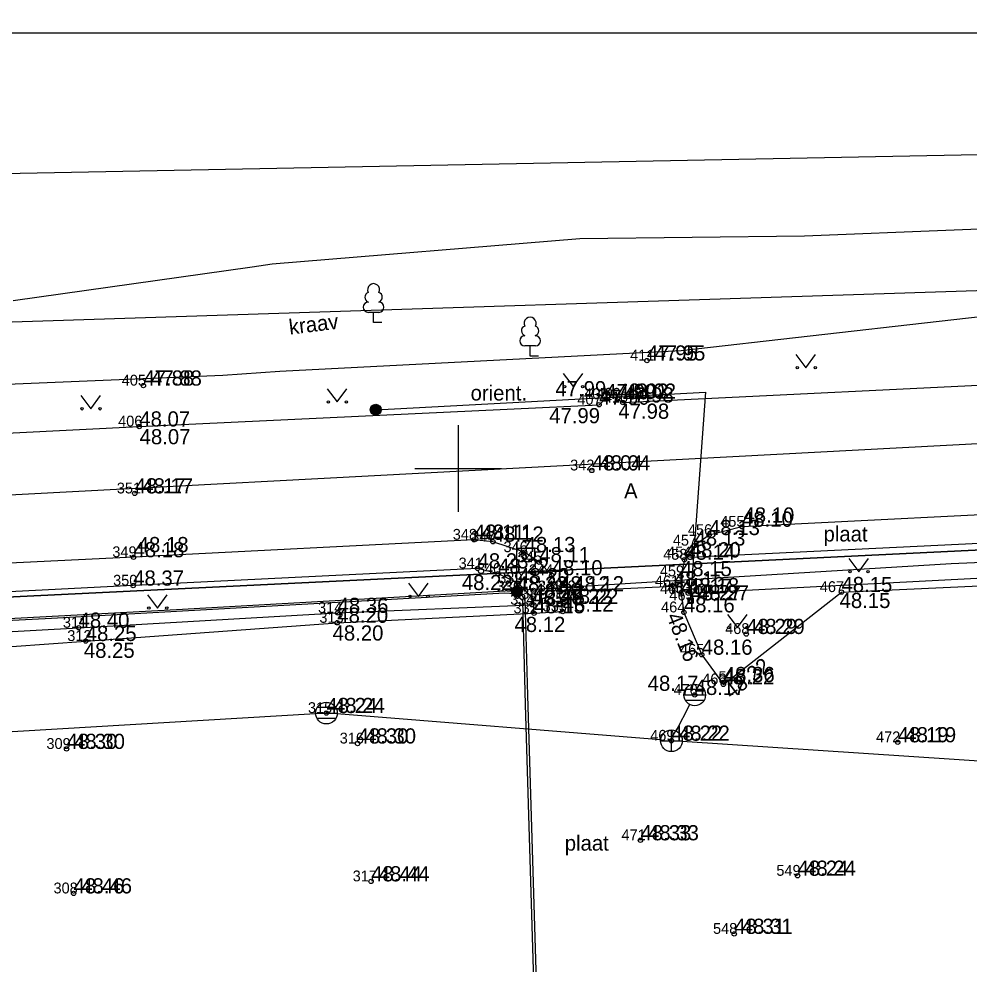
# Model space of a CAD drawing. Extents: x 640876 to 641418, y 6455595 to 6456085.
# Drawn here: x 641129.76 to 641173.59, y 6455977.11 to 6456020.73 of the extents above; entities that cross this region are included whole.
import ezdxf

# ---------------------------------------------------------------- set-up
doc = ezdxf.new("R2010")
doc.units = 0
for name, color, linetype in [('AED', 7, 'Continuous'), ('HALJASTUS', 7, 'Continuous'), ('KKAEV', 7, 'Continuous'), ('KORGUS', 7, 'Continuous'), ('MOOTKORG', 7, 'Continuous'), ('MOOTMPUNKT', 7, 'Continuous'), ('MOOTNR', 7, 'Continuous'), ('MOOTPIIR', 7, 'Continuous'), ('MPKAABEL', 7, 'Continuous'), ('PIIR', 7, 'Continuous'), ('POST', 7, 'Continuous'), ('PUU', 7, 'Continuous'), ('RAJATIS', 7, 'Continuous'), ('SKKAEV', 7, 'Continuous'), ('SKTRASS', 7, 'Continuous'), ('TEE', 7, 'Continuous'), ('VEEKOGU', 7, 'Continuous'), ('VORK', 7, 'Continuous'), ('VORMISTUS', 7, 'Continuous'), ('VTRASS', 7, 'Continuous')]:
    doc.layers.add(name, color=color, linetype=linetype)

msp = doc.modelspace()

# ---------------------------------------------------------------- linework, layer by layer
at = {"layer": 'AED'}
for p, q in [((641154.564, 6455993.886), (641154.564, 6455993.636)), ((641154.564, 6455993.886), (641154.814, 6455993.886)), ((641154.814, 6455993.886), (641154.814, 6455993.636)), ((641160.586, 6455994.045), (641160.586, 6455993.795)), ((641160.586, 6455994.045), (641160.836, 6455994.045)), ((641160.836, 6455994.045), (641160.836, 6455993.795)), ((641154.564, 6455993.636), (641154.814, 6455993.636)), ((641160.586, 6455993.795), (641160.836, 6455993.795))]:
    msp.add_line(p, q, dxfattribs=at)
for points in [[(641160.606, 6455994.253), (641178.047, 6455995.168), (641191.652, 6455995.856), (641207.752, 6455996.687), (641222.341, 6455997.449), (641221.765, 6455994.718), (641219.959, 6455985.906), (641217.708, 6455975.561), (641214.2, 6455967.017), (641207.311, 6455950.541), (641202.719, 6455939.647), (641198.916, 6455930.446)], [(641087.994, 6455978.931), (641096.846, 6455989.854), (641117.445, 6455991.822), (641132.506, 6455992.659), (641144.443, 6455993.343), (641153.401, 6455993.722)]]:
    msp.add_lwpolyline(points, dxfattribs=at)
at = {"layer": 'HALJASTUS'}
for p, q in [((641165.567, 6456005.256), (641166.03, 6456004.649)), ((641166.03, 6456004.649), (641166.476, 6456005.256)), ((641154.842, 6456004.388), (641155.305, 6456003.781)), ((641155.305, 6456003.781), (641155.751, 6456004.388)), ((641143.96, 6456003.678), (641144.423, 6456003.071)), ((641144.423, 6456003.071), (641144.869, 6456003.678)), ((641132.604, 6456003.362), (641133.067, 6456002.755)), ((641133.067, 6456002.755), (641133.513, 6456003.362)), ((641167.999, 6455995.846), (641168.463, 6455995.24)), ((641168.463, 6455995.24), (641168.908, 6455995.846)), ((641147.713, 6455994.714), (641148.177, 6455994.107)), ((641148.177, 6455994.107), (641148.622, 6455994.714)), ((641135.682, 6455994.173), (641136.145, 6455993.566)), ((641136.145, 6455993.566), (641136.591, 6455994.173)), ((641162.412, 6455993.276), (641162.875, 6455992.67)), ((641162.875, 6455992.67), (641163.321, 6455993.276))]:
    msp.add_line(p, q, dxfattribs=at)
for centre in [(641165.629, 6456004.649), (641166.458, 6456004.649), (641154.904, 6456003.781), (641155.733, 6456003.781), (641144.022, 6456003.071), (641144.851, 6456003.071), (641132.666, 6456002.755), (641133.495, 6456002.755), (641168.062, 6455995.24), (641168.89, 6455995.24), (641147.776, 6455994.107), (641148.604, 6455994.107), (641135.744, 6455993.566), (641136.573, 6455993.566), (641162.474, 6455992.67), (641163.303, 6455992.67)]:
    msp.add_circle(centre, 0.055, dxfattribs=at)
at = {"layer": 'KKAEV'}
for p, q in [((641159.828, 6455986.948), (641159.828, 6455987.948)), ((641159.328, 6455987.448), (641160.328, 6455987.448))]:
    msp.add_line(p, q, dxfattribs=at)
msp.add_circle((641159.828, 6455987.448), 0.5, dxfattribs=at)
at = {"layer": 'KORGUS'}
for centre in [(641158.702, 6456004.981), (641135.496, 6456003.825), (641156.781, 6456003.203), (641157.348, 6456003.221), (641157.594, 6456003.045), (641156.494, 6456002.943), (641135.305, 6456001.938), (641156.161, 6455999.912), (641135.093, 6455998.852), (641163.081, 6455997.316), (641150.727, 6455996.717), (641135.038, 6455995.912), (641152.702, 6455994.325), (641152.705, 6455994.33), (641167.668, 6455994.304), (641160.711, 6455993.92), (641154.689, 6455993.761), (641154.822, 6455993.407), (641160.404, 6455993.367), (641144.43, 6455992.887), (641132.837, 6455992.048), (641163.282, 6455992.37), (641162.227, 6455990.048), (641160.902, 6455989.559), (641143.927, 6455988.726), (641145.367, 6455987.321), (641159.828, 6455987.448), (641170.261, 6455987.376), (641131.95, 6455987.07), (641158.403, 6455982.857), (641165.642, 6455981.221), (641145.99, 6455980.965), (641132.276, 6455980.408), (641162.723, 6455978.543)]:
    msp.add_circle(centre, 0.1, dxfattribs=at)
at = {"layer": 'MOOTMPUNKT'}
for centre in [(641158.702, 6456004.981), (641135.496, 6456003.825), (641156.781, 6456003.203), (641157.348, 6456003.221), (641157.594, 6456003.045), (641156.494, 6456002.943), (641135.305, 6456001.938), (641156.161, 6455999.912), (641135.093, 6455998.852), (641163.081, 6455997.316), (641161.565, 6455996.932), (641150.727, 6455996.717), (641151.601, 6455996.628), (641160.895, 6455996.447), (641153.065, 6455996.145), (641135.038, 6455995.912), (641153.74, 6455995.681), (641160.425, 6455995.795), (641160.679, 6455995.901), (641150.896, 6455995.393), (641151.844, 6455995.148), (641152.772, 6455994.709), (641154.316, 6455995.079), (641160.271, 6455995.032), (641135.023, 6455994.601), (641152.702, 6455994.325), (641152.705, 6455994.33), (641154.653, 6455994.333), (641155.303, 6455994.339), (641159.942, 6455994.565), (641160.279, 6455994.218), (641160.606, 6455994.253), (641167.668, 6455994.304), (641153.465, 6455993.996), (641160.711, 6455993.92), (641144.443, 6455993.343), (641153.401, 6455993.722), (641154.689, 6455993.761), (641154.822, 6455993.407), (641160.404, 6455993.367), (641153.501, 6455993.325), (641132.506, 6455992.659), (641144.43, 6455992.887), (641132.837, 6455992.048), (641163.282, 6455992.37), (641161.226, 6455991.415), (641162.227, 6455990.048), (641162.246, 6455990.152), (641160.902, 6455989.559), (641143.927, 6455988.726), (641145.367, 6455987.321), (641159.828, 6455987.448), (641170.261, 6455987.376), (641131.95, 6455987.07), (641158.403, 6455982.857), (641165.642, 6455981.221), (641145.99, 6455980.965), (641132.276, 6455980.408), (641162.723, 6455978.543)]:
    msp.add_circle(centre, 0.1, dxfattribs=at)
at = {"layer": 'MOOTPIIR'}
msp.add_lwpolyline([(641060.916, 6455895.936), (641100.061, 6455950.482), (641099.586, 6455952.159), (641069.132, 6455984.035), (641066.132, 6455988.623), (641076.463, 6456005.049), (641230.642, 6456010.048), (641237.36, 6455995.24), (641237.24, 6455992.81), (641236.258, 6455990.888), (641229.041, 6455971.315), (641203.026, 6455909.57), (641225.257, 6455906.847), (641239.512, 6455898.491), (641200.195, 6455851.697), (641192.016, 6455859.099), (641169.785, 6455829.138), (641192.025, 6455807.568), (641252.96, 6455758.075), (641231.388, 6455736.74), (641191.474, 6455775.975), (641152.419, 6455787.914), (641136.351, 6455788.307), (641049.066, 6455856.043)], dxfattribs=at)
at = {"layer": 'MPKAABEL'}
for points in [[(641146.199, 6456002.712), (641161.408, 6456003.528), (641160.711, 6455994.045)], [(641152.745, 6455994.399), (641157.936, 6455994.715), (641172.717, 6455995.627), (641184.197, 6455996.113), (641197.79, 6455997.111), (641207.568, 6455997.528), (641217.849, 6455998.12), (641221.671, 6455998.134)], [(641081.282, 6455986.001), (641083.826, 6455989.191), (641093.656, 6455990.177), (641101.434, 6455990.689), (641109.211, 6455991.201), (641116.735, 6455992.286), (641117.253, 6455992.438), (641137.02, 6455993.508), (641152.446, 6455994.375), (641152.745, 6455994.399), (641153.077, 6455993.956), (641153.192, 6455989.529), (641153.743, 6455971.272), (641153.877, 6455968.765), (641154.087, 6455964.787), (641154.134, 6455960.265)], [(641154.034, 6455960.264), (641153.95, 6455965.518), (641153.778, 6455968.761), (641153.643, 6455971.268), (641153.102, 6455989.126), (641152.978, 6455993.905), (641152.599, 6455994.224), (641152.147, 6455994.252), (641142.791, 6455993.73), (641131.26, 6455993.087), (641117.217, 6455992.367), (641116.76, 6455992.188), (641112.991, 6455991.645), (641109.221, 6455991.101), (641101.443, 6455990.589), (641093.665, 6455990.077), (641088.757, 6455989.569), (641083.848, 6455989.06), (641081.36, 6455985.939)]]:
    msp.add_lwpolyline(points, dxfattribs=at)
at = {"layer": 'PIIR'}
for points in [[(640981.25, 6456014.49), (641018.11, 6456020.73), (641048.89, 6456017.91), (641071.8, 6456014.51), (641086.43, 6456012.78), (641194.48, 6456014.88), (641224.33, 6456016.64), (641234.96, 6456017.83), (641241.97, 6456004.88), (641237.36, 6455995.24), (641222.58, 6455998.61), (641084.84, 6455991.92), (641061.51, 6455993.34), (640998.61, 6455989.99), (640969.54, 6455988.44)], [(641222.58, 6455998.61), (641237.36, 6455995.24), (641235.34, 6455991.29), (641228.11, 6455971.68), (641220.5, 6455953.19), (641213.41, 6455936.25), (641201.58, 6455908.74), (641224.93, 6455905.88), (641191.87, 6455860.58), (641157.02, 6455885.66), (641160.91, 6455891.99), (641102.26, 6455951.82), (641074.95, 6455979.64), (641084.84, 6455991.92)]]:
    msp.add_lwpolyline(points, close=True, dxfattribs=at)
at = {"layer": 'POST'}
for p, q in [((641152.702, 6455994.575), (641152.702, 6455996.575)), ((641152.702, 6455996.325), (641153.702, 6455996.325)), ((641152.929, 6455996.004), (641152.929, 6455996.325)), ((641153.541, 6455996.004), (641153.541, 6455996.325)), ((641152.702, 6455994.325), (641152.702, 6455994.325))]:
    msp.add_line(p, q, dxfattribs=at)
for radius in [0.25, 0.225, 0.2, 0.175, 0.15, 0.125, 0.1, 0.075, 0.05, 0.025]:
    msp.add_circle((641152.705, 6455994.33), radius, dxfattribs=at)
msp.add_arc((641153.235, 6455996.004), 0.306, 180, 0, dxfattribs=at)
at = {"layer": 'PUU'}
for p, q in [((641146.342, 6456007.204), (641145.862, 6456007.204)), ((641146.102, 6456006.729), (641146.102, 6456007.204)), ((641146.482, 6456006.729), (641146.102, 6456006.729)), ((641153.558, 6456005.654), (641153.078, 6456005.654)), ((641153.318, 6456005.179), (641153.318, 6456005.654)), ((641153.698, 6456005.179), (641153.318, 6456005.179))]:
    msp.add_line(p, q, dxfattribs=at)
for centre, radius, start, end in [((641146.102, 6456008.249), 0.277, 332.5799, 207.4201), ((641145.932, 6456007.901), 0.233, 109.0217, 253.1415), ((641146.272, 6456007.901), 0.233, 286.8508, 70.9859), ((641145.864, 6456007.441), 0.238, 90.0016, 269.3953), ((641146.339, 6456007.441), 0.238, 270.6047, 89.9984), ((641153.318, 6456006.699), 0.277, 332.5799, 207.4201), ((641153.148, 6456006.351), 0.233, 109.0217, 253.1415), ((641153.488, 6456006.351), 0.233, 286.8508, 70.9859), ((641153.08, 6456005.891), 0.238, 90.0016, 269.3953), ((641153.555, 6456005.891), 0.238, 270.6047, 89.9984)]:
    msp.add_arc(centre, radius, start, end, dxfattribs=at)
at = {"layer": 'RAJATIS'}
for radius in [0.25, 0.225, 0.2, 0.175, 0.15, 0.125, 0.1, 0.075, 0.05, 0.025]:
    msp.add_circle((641146.199, 6456002.712), radius, dxfattribs=at)
at = {"layer": 'SKKAEV'}
for p, q in [((641160.402, 6455989.559), (641161.402, 6455989.559)), ((641161.332, 6455989.809), (641160.472, 6455989.809)), ((641161.332, 6455989.309), (641160.472, 6455989.309)), ((641143.427, 6455988.726), (641144.427, 6455988.726)), ((641144.357, 6455988.976), (641143.497, 6455988.976)), ((641144.357, 6455988.476), (641143.497, 6455988.476))]:
    msp.add_line(p, q, dxfattribs=at)
for centre in [(641160.902, 6455989.559), (641143.927, 6455988.726)]:
    msp.add_circle(centre, 0.5, dxfattribs=at)
at = {"layer": 'SKTRASS'}
for points in [[(641160.055, 6455987.894), (641160.676, 6455989.113)], [(641143.428, 6455988.697), (641126.323, 6455987.679)], [(641159.33, 6455987.488), (641144.413, 6455988.687)], [(641177.042, 6455986.303), (641160.327, 6455987.415)]]:
    msp.add_lwpolyline(points, dxfattribs=at)
at = {"layer": 'TEE'}
for points in [[(641157.348, 6456003.221), (641157.594, 6456003.045), (641177.755, 6456004.027), (641177.971, 6456004.29)], [(641114.891, 6456001.167), (641115.111, 6456000.924), (641135.305, 6456001.938), (641156.494, 6456002.943), (641156.781, 6456003.203)], [(641222.651, 6455997.98), (641222.677, 6455998.823), (641220.802, 6456000.252), (641207.904, 6455999.587), (641192.028, 6455998.799), (641178.983, 6455998.116), (641163.081, 6455997.316), (641161.565, 6455996.932), (641160.895, 6455996.447), (641160.425, 6455995.795), (641160.271, 6455995.032), (641160.279, 6455994.218), (641160.404, 6455993.367), (641161.226, 6455991.415), (641162.227, 6455990.048), (641167.668, 6455994.304), (641183.068, 6455995.004), (641194.491, 6455995.56), (641201.796, 6455995.908), (641207.259, 6455996.159), (641208.614, 6455995.025), (641219.562, 6455985.852), (641216.822, 6455976.794)], [(641222.264, 6455998.978), (641207.946, 6455998.252), (641191.921, 6455997.451), (641178.778, 6455996.781), (641160.679, 6455995.901)], [(641088.432, 6455978.324), (641097.01, 6455989.437), (641117.484, 6455990.932), (641132.837, 6455992.048), (641144.43, 6455992.887), (641153.501, 6455993.325), (641154.822, 6455993.407), (641154.653, 6455994.333), (641154.316, 6455995.079), (641153.74, 6455995.681), (641153.065, 6455996.145), (641151.601, 6455996.628), (641150.727, 6455996.717), (641135.038, 6455995.912), (641116.951, 6455995.037), (641097.835, 6455994.027), (641080.247, 6455993.161), (641080.246, 6455993.162), (641078.083, 6455992.591), (641077.94, 6455991.681), (641080.556, 6455991.837)], [(641153.501, 6455993.325), (641153.465, 6455993.996), (641152.772, 6455994.709), (641151.844, 6455995.148), (641150.896, 6455995.393), (641135.023, 6455994.601), (641116.405, 6455993.654), (641097.851, 6455992.703), (641080.556, 6455991.837)], [(641154.653, 6455994.333), (641160.259, 6455994.596)]]:
    msp.add_lwpolyline(points, dxfattribs=at)
at = {"layer": 'VEEKOGU'}
for points in [[(641129.494, 6456007.757), (641140.506, 6456009.297), (641141.425, 6456009.442), (641155.616, 6456010.605), (641165.969, 6456010.733), (641179.754, 6456011.289), (641189.024, 6456012.987)], [(641209.122, 6456009.547), (641192.523, 6456008.523), (641178.117, 6456007.452), (641160.284, 6456005.431), (641141.785, 6456004.469), (641139.156, 6456004.288), (641122.94, 6456003.612)]]:
    msp.add_lwpolyline(points, dxfattribs=at)
at = {"layer": 'VORK'}
for p, q in [((641150, 6456002), (641150, 6455998)), ((641148, 6456000), (641152, 6456000))]:
    msp.add_line(p, q, dxfattribs=at)
at = {"layer": 'VORMISTUS'}
msp.add_line((641035.115, 6456020.09), (641256.302, 6456020.09), dxfattribs=at)
at = {"layer": 'VTRASS'}
msp.add_lwpolyline([(641064.363, 6455995.75), (641076.979, 6455996.021), (641104.204, 6455997.462), (641127.864, 6455998.715), (641152.811, 6456000.037), (641188.143, 6456001.908), (641203.655, 6456002.73), (641225.036, 6456004.365)], dxfattribs=at)

# ---------------------------------------------------------------- texts
at = {"layer": 'KORGUS'}
for s, p in [('47.95', (641159.052, 6456004.981)), ('47.88', (641135.846, 6456003.825)), ('47.99', (641154.483, 6456003.333)), ('48.02', (641157.698, 6456003.221)), ('47.99', (641154.196, 6456002.09)), ('47.98', (641157.385, 6456002.296)), ('48.07', (641135.32, 6456001.12)), ('48.04', (641156.511, 6455999.912)), ('48.17', (641135.443, 6455998.852)), ('48.10', (641163.152, 6455997.508)), ('48.11', (641151.077, 6455996.717)), ('48.18', (641135.233, 6455996.144)), ('48.22', (641150.171, 6455994.398)), ('48.22', (641155.039, 6455993.761)), ('48.27', (641161.061, 6455993.92)), ('48.15', (641167.581, 6455993.568)), ('48.12', (641152.597, 6455992.463)), ('48.29', (641163.632, 6455992.37)), ('48.20', (641144.213, 6455992.069)), ('48.25', (641132.75, 6455991.27)), ('48.17', (641158.736, 6455989.75)), ('48.24', (641144.277, 6455988.726)), ('48.30', (641132.3, 6455987.07)), ('48.30', (641145.717, 6455987.321)), ('48.22', (641160.178, 6455987.448)), ('48.19', (641170.611, 6455987.376)), ('48.33', (641158.753, 6455982.857)), ('48.44', (641146.34, 6455980.965)), ('48.24', (641165.992, 6455981.221)), ('48.46', (641132.626, 6455980.408)), ('48.31', (641163.073, 6455978.543))]:
    msp.add_text(s, height=0.7, dxfattribs=at).set_placement(p)
for s, rotation, p in [('48.16', 291.9302, (641159.585, 6455993.194)), ('48.22', 37.3588, (641162.598, 6455989.346))]:
    msp.add_text(s, height=0.7, rotation=rotation, dxfattribs=at).set_placement(p)
at = {"layer": 'MOOTKORG'}
for s, p in [('47.95', (641158.702, 6456004.981)), ('47.88', (641135.496, 6456003.825)), ('47.99', (641156.494, 6456002.943)), ('47.99', (641156.781, 6456003.203)), ('48.02', (641157.348, 6456003.221)), ('47.98', (641157.594, 6456003.045)), ('48.07', (641135.305, 6456001.938)), ('48.04', (641156.161, 6455999.912)), ('48.17', (641135.093, 6455998.852)), ('48.10', (641163.081, 6455997.316)), ('48.11', (641150.727, 6455996.717)), ('48.13', (641161.565, 6455996.932)), ('48.12', (641151.601, 6455996.628)), ('48.13', (641160.895, 6455996.447)), ('48.18', (641135.038, 6455995.912)), ('48.13', (641153.065, 6455996.145)), ('48.14', (641160.425, 6455995.795)), ('48.20', (641160.679, 6455995.901)), ('48.23', (641150.896, 6455995.393)), ('48.11', (641153.74, 6455995.681)), ('48.22', (641151.844, 6455995.148)), ('48.10', (641154.316, 6455995.079)), ('48.15', (641160.271, 6455995.032)), ('48.37', (641135.023, 6455994.601)), ('48.20', (641152.772, 6455994.709)), ('48.15', (641159.942, 6455994.565)), ('48.22', (641152.702, 6455994.325)), ('48.22', (641152.705, 6455994.33)), ('48.12', (641154.653, 6455994.333)), ('48.12', (641155.303, 6455994.339)), ('48.17', (641160.279, 6455994.218)), ('48.18', (641160.606, 6455994.253)), ('48.15', (641167.668, 6455994.304)), ('48.29', (641153.401, 6455993.722)), ('48.22', (641153.465, 6455993.996)), ('48.22', (641154.689, 6455993.761)), ('48.27', (641160.711, 6455993.92)), ('48.36', (641144.443, 6455993.343)), ('48.15', (641153.501, 6455993.325)), ('48.12', (641154.822, 6455993.407)), ('48.16', (641160.404, 6455993.367)), ('48.20', (641144.43, 6455992.887)), ('48.40', (641132.506, 6455992.659)), ('48.29', (641163.282, 6455992.37)), ('48.25', (641132.837, 6455992.048)), ('48.16', (641161.226, 6455991.415)), ('48.36', (641162.246, 6455990.152)), ('48.22', (641162.227, 6455990.048)), ('48.17', (641160.902, 6455989.559)), ('48.24', (641143.927, 6455988.726)), ('48.30', (641131.95, 6455987.07)), ('48.30', (641145.367, 6455987.321)), ('48.22', (641159.828, 6455987.448)), ('48.19', (641170.261, 6455987.376)), ('48.33', (641158.403, 6455982.857)), ('48.44', (641145.99, 6455980.965)), ('48.24', (641165.642, 6455981.221)), ('48.46', (641132.276, 6455980.408)), ('48.31', (641162.723, 6455978.543))]:
    msp.add_text(s, height=0.7, dxfattribs=at).set_placement(p)
at = {"layer": 'MOOTNR'}
for s, p in [('411', (641157.927, 6456004.981)), ('405', (641134.496, 6456003.825)), ('408', (641155.806, 6456003.203)), ('409', (641156.374, 6456003.221)), ('410', (641156.719, 6456003.045)), ('407', (641155.494, 6456002.943)), ('406', (641134.33, 6456001.938)), ('342', (641155.161, 6455999.912)), ('351', (641134.268, 6455998.852)), ('455', (641162.081, 6455997.316)), ('456', (641160.59, 6455996.932)), ('348', (641149.752, 6455996.717)), ('347', (641150.601, 6455996.628)), ('457', (641159.895, 6455996.447)), ('346', (641152.09, 6455996.145)), ('349', (641134.063, 6455995.912)), ('345', (641152.74, 6455995.681)), ('458', (641159.451, 6455995.795)), ('454', (641159.629, 6455995.901)), ('341', (641150.021, 6455995.393)), ('340', (641150.869, 6455995.148)), ('339', (641151.847, 6455994.709)), ('344', (641153.266, 6455995.079)), ('459', (641159.296, 6455995.032)), ('350', (641134.098, 6455994.601)), ('337', (641151.755, 6455994.33)), ('336', (641151.777, 6455994.325)), ('343', (641153.678, 6455994.333)), ('462', (641154.303, 6455994.339)), ('461', (641159.067, 6455994.565)), ('453', (641159.631, 6455994.253)), ('467', (641166.669, 6455994.304)), ('338', (641152.54, 6455993.996)), ('460', (641159.304, 6455994.218)), ('463', (641159.736, 6455993.92)), ('334', (641152.401, 6455993.722)), ('335', (641153.739, 6455993.761)), ('333', (641153.897, 6455993.407)), ('464', (641159.355, 6455993.367)), ('314', (641143.543, 6455993.343)), ('332', (641152.551, 6455993.325)), ('311', (641131.781, 6455992.659)), ('313', (641143.605, 6455992.887)), ('312', (641131.988, 6455992.048)), ('468', (641162.307, 6455992.37)), ('465', (641160.226, 6455991.415)), ('466', (641161.252, 6455990.048)), ('5', (641161.996, 6455990.152)), ('470', (641159.928, 6455989.559)), ('315', (641143.077, 6455988.726)), ('316', (641144.542, 6455987.321)), ('469', (641158.854, 6455987.448)), ('472', (641169.261, 6455987.376)), ('309', (641131.025, 6455987.07)), ('471', (641157.528, 6455982.857)), ('549', (641164.667, 6455981.221)), ('317', (641145.14, 6455980.965)), ('308', (641131.351, 6455980.408)), ('548', (641161.748, 6455978.543))]:
    msp.add_text(s, height=0.5, dxfattribs=at).set_placement(p)
at = {"layer": 'MPKAABEL'}
msp.add_text('orient.', height=0.7, dxfattribs=at).set_placement((641150.574, 6456003.138))
at = {"layer": 'TEE'}
for s, p in [('A', (641157.648, 6455998.621)), ('plaat', (641166.84, 6455996.638)), ('plaat', (641154.914, 6455982.38))]:
    msp.add_text(s, height=0.7, dxfattribs=at).set_placement(p)
at = {"layer": 'VEEKOGU'}
msp.add_text('kraav', height=0.7, rotation=7.0296, dxfattribs=at).set_placement((641142.243, 6456006.173))

doc.saveas('drawing.dxf')
